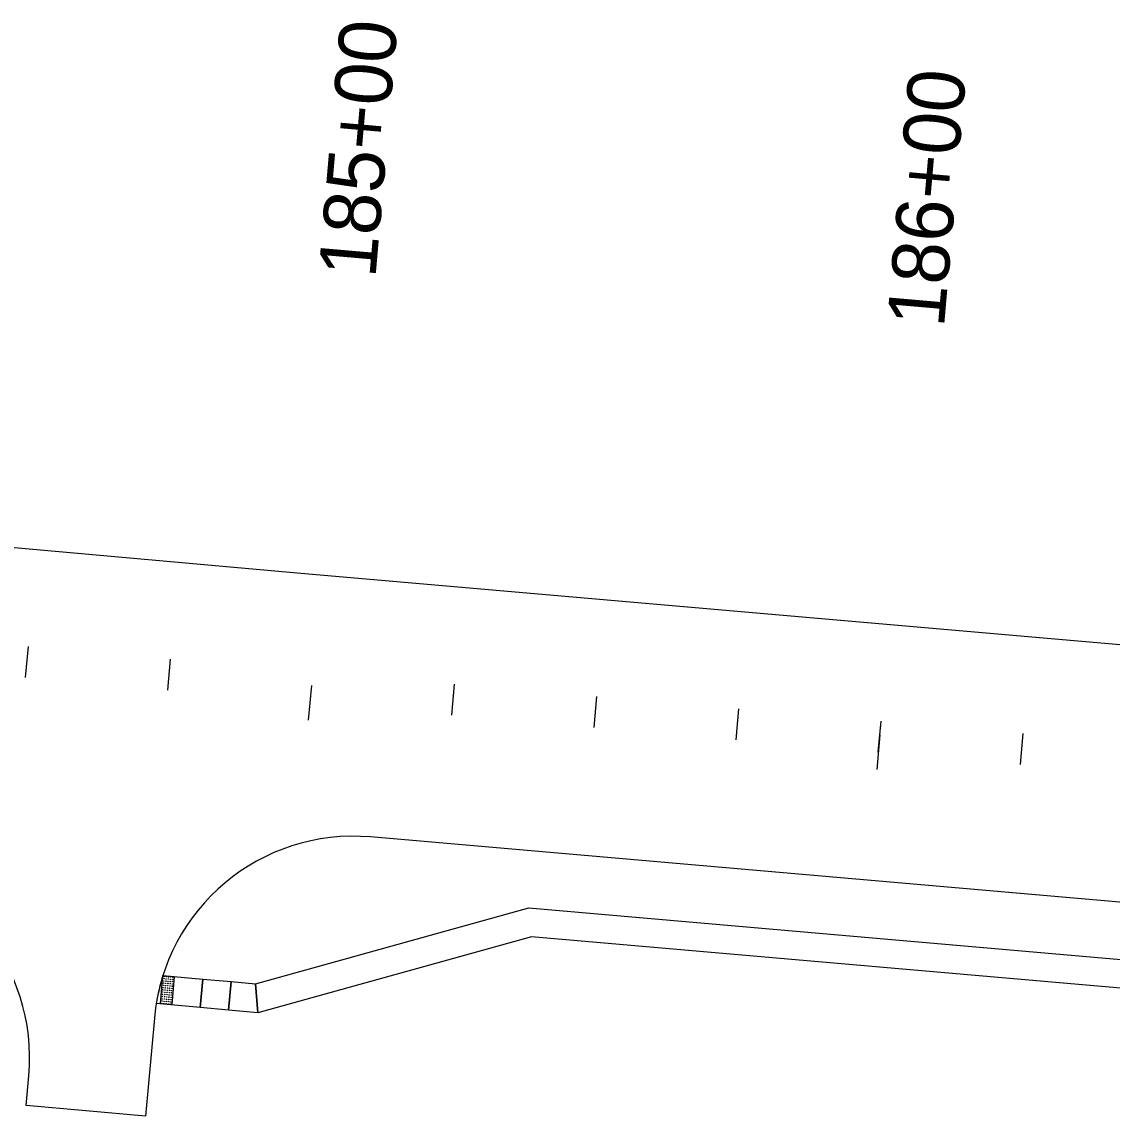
# Model space of a CAD drawing. Extents: x 20499216 to 20505321, y 7953487 to 7960535.
# Drawn here: x 20502156.3 to 20502347.4, y 7953782.6 to 7953974.4 of the extents above; entities that cross this region are included whole.
import ezdxf

# ---------------------------------------------------------------- set-up
doc = ezdxf.new("R2010")
doc.units = 0
for name, color, linetype in [('Drainage', 7, 'Continuous'), ('EXT_CU', 7, 'Continuous'), ('EXT_RR', 7, 'Continuous'), ('NamedBoundary', 7, 'Continuous'), ('Roadways', 7, 'Continuous'), ('Safety', 7, 'Continuous')]:
    doc.layers.add(name, color=color, linetype=linetype)

msp = doc.modelspace()

# ---------------------------------------------------------------- linework, layer by layer
at = {"layer": 'Drainage'}
msp.add_lwpolyline([(20502181.04, 7953807.25), (20502188.02, 7953806.62), (20502187.57, 7953801.64), (20502179.87, 7953802.33)], dxfattribs=at)
msp.add_lwpolyline([(20502197.71, 7953800.73), (20502192.55, 7953801.2), (20502193, 7953806.18), (20502197.25, 7953805.8)], close=True, dxfattribs=at)
for centre in [(20502182.5, 7953803.44), (20502182.53, 7953803.83)]:
    msp.add_circle(centre, 0.0375, dxfattribs=at)
msp.add_arc((20502214.41, 7953796.67), 35, 162.4173, 170.6968, dxfattribs=at)
at = {"layer": 'EXT_CU'}
for p, q in [((20502180.6, 7953802.27), (20502181.04, 7953807.25)), ((20502181.04, 7953807.25), (20502183.04, 7953807.07)), ((20502183.04, 7953807.07), (20502182.59, 7953802.09)), ((20502182.59, 7953802.09), (20502180.6, 7953802.27))]:
    msp.add_line(p, q, dxfattribs=at)
msp.add_lwpolyline([(20502501.09, 7953791.77), (20502245.65, 7953814.03), (20502197.71, 7953800.73), (20502197.25, 7953805.8), (20502245.18, 7953819.09), (20502501.52, 7953796.76)], close=True, dxfattribs=at)
for centre, radius in [((20502181.25, 7953807.09), 0.0375), ((20502181.25, 7953807.09), 0.0187), ((20502181.64, 7953807.05), 0.0375), ((20502181.64, 7953807.05), 0.0187), ((20502182.03, 7953807.02), 0.0375), ((20502182.03, 7953807.02), 0.0187), ((20502182.42, 7953806.98), 0.0375), ((20502182.42, 7953806.98), 0.0187), ((20502182.81, 7953806.95), 0.0375), ((20502182.81, 7953806.95), 0.0187), ((20502181.08, 7953805.14), 0.0375), ((20502181.08, 7953805.14), 0.0187), ((20502181.11, 7953805.53), 0.0375), ((20502181.11, 7953805.53), 0.0187), ((20502181.15, 7953805.92), 0.0375), ((20502181.15, 7953805.92), 0.0187), ((20502181.18, 7953806.31), 0.0375), ((20502181.18, 7953806.31), 0.0187), ((20502181.22, 7953806.7), 0.0375), ((20502181.22, 7953806.7), 0.0187), ((20502181.47, 7953805.1), 0.0375), ((20502181.47, 7953805.1), 0.0187), ((20502181.5, 7953805.49), 0.0375), ((20502181.5, 7953805.49), 0.0187), ((20502181.54, 7953805.88), 0.0375), ((20502181.54, 7953805.88), 0.0187), ((20502181.57, 7953806.27), 0.0375), ((20502181.57, 7953806.27), 0.0187), ((20502181.61, 7953806.66), 0.0375), ((20502181.61, 7953806.66), 0.0187), ((20502181.86, 7953805.07), 0.0375), ((20502181.86, 7953805.07), 0.0187), ((20502181.89, 7953805.46), 0.0375), ((20502181.89, 7953805.46), 0.0187), ((20502181.93, 7953805.85), 0.0375), ((20502181.93, 7953805.85), 0.0187), ((20502181.96, 7953806.24), 0.0375), ((20502181.96, 7953806.24), 0.0187), ((20502182, 7953806.63), 0.0375), ((20502182, 7953806.63), 0.0187), ((20502182.25, 7953805.03), 0.0375), ((20502182.25, 7953805.03), 0.0187), ((20502182.28, 7953805.42), 0.0375), ((20502182.28, 7953805.42), 0.0187), ((20502182.32, 7953805.81), 0.0375), ((20502182.32, 7953805.81), 0.0187), ((20502182.35, 7953806.2), 0.0375), ((20502182.35, 7953806.2), 0.0187), ((20502182.39, 7953806.59), 0.0375), ((20502182.39, 7953806.59), 0.0187), ((20502182.64, 7953805), 0.0375), ((20502182.64, 7953805), 0.0187), ((20502182.67, 7953805.39), 0.0375), ((20502182.67, 7953805.39), 0.0187), ((20502182.71, 7953805.78), 0.0375), ((20502182.71, 7953805.78), 0.0187), ((20502182.74, 7953806.17), 0.0375), ((20502182.74, 7953806.17), 0.0187), ((20502182.78, 7953806.56), 0.0375), ((20502182.78, 7953806.56), 0.0187), ((20502180.9, 7953803.16), 0.0375), ((20502180.9, 7953803.16), 0.0187), ((20502180.94, 7953803.58), 0.0375), ((20502180.94, 7953803.58), 0.0187), ((20502180.97, 7953803.97), 0.0375), ((20502180.97, 7953803.97), 0.0187), ((20502181.01, 7953804.36), 0.0375), ((20502181.01, 7953804.36), 0.0187), ((20502181.04, 7953804.75), 0.0375), ((20502181.04, 7953804.75), 0.0187), ((20502181.29, 7953803.13), 0.0375), ((20502181.29, 7953803.13), 0.0187), ((20502181.33, 7953803.54), 0.0375), ((20502181.33, 7953803.54), 0.0187), ((20502181.36, 7953803.93), 0.0375), ((20502181.36, 7953803.93), 0.0187), ((20502181.4, 7953804.32), 0.0375), ((20502181.4, 7953804.32), 0.0187), ((20502181.43, 7953804.71), 0.0375), ((20502181.43, 7953804.71), 0.0187), ((20502181.68, 7953803.09), 0.0375), ((20502181.68, 7953803.09), 0.0187), ((20502181.72, 7953803.51), 0.0375), ((20502181.72, 7953803.51), 0.0187), ((20502181.75, 7953803.9), 0.0375), ((20502181.75, 7953803.9), 0.0187), ((20502181.79, 7953804.29), 0.0375), ((20502181.79, 7953804.29), 0.0187), ((20502181.82, 7953804.68), 0.0375), ((20502181.82, 7953804.68), 0.0187), ((20502182.07, 7953803.06), 0.0375), ((20502182.07, 7953803.06), 0.0187), ((20502182.11, 7953803.47), 0.0375), ((20502182.11, 7953803.47), 0.0187), ((20502182.14, 7953803.86), 0.0375), ((20502182.14, 7953803.86), 0.0187), ((20502182.18, 7953804.25), 0.0375), ((20502182.18, 7953804.25), 0.0187), ((20502182.21, 7953804.64), 0.0375), ((20502182.21, 7953804.64), 0.0187), ((20502182.46, 7953803.02), 0.0375), ((20502182.46, 7953803.02), 0.0187), ((20502182.5, 7953803.44), 0.0375), ((20502182.5, 7953803.44), 0.0187), ((20502182.53, 7953803.83), 0.0375), ((20502182.53, 7953803.83), 0.0187), ((20502182.57, 7953804.22), 0.0375), ((20502182.57, 7953804.22), 0.0187), ((20502182.6, 7953804.61), 0.0375), ((20502182.6, 7953804.61), 0.0187), ((20502180.83, 7953802.38), 0.0375), ((20502180.83, 7953802.38), 0.0187), ((20502180.87, 7953802.77), 0.0375), ((20502180.87, 7953802.77), 0.0187), ((20502181.22, 7953802.35), 0.0375), ((20502181.22, 7953802.35), 0.0187), ((20502181.26, 7953802.74), 0.0375), ((20502181.26, 7953802.74), 0.0187), ((20502181.61, 7953802.31), 0.0375), ((20502181.61, 7953802.31), 0.0187), ((20502181.65, 7953802.7), 0.0375), ((20502181.65, 7953802.7), 0.0187), ((20502182, 7953802.28), 0.0375), ((20502182, 7953802.28), 0.0187), ((20502182.04, 7953802.67), 0.0375), ((20502182.04, 7953802.67), 0.0187), ((20502182.39, 7953802.24), 0.0375), ((20502182.39, 7953802.24), 0.0187), ((20502182.43, 7953802.63), 0.0375), ((20502182.43, 7953802.63), 0.0187)]:
    msp.add_circle(centre, radius, dxfattribs=at)
at = {"layer": 'EXT_RR'}
for p, q in [((20502156.99, 7953859.5), (20502157.48, 7953864.94)), ((20502181.89, 7953857.27), (20502182.38, 7953862.71)), ((20502207.06, 7953858.1), (20502206.52, 7953852.01)), ((20502231.7, 7953852.89), (20502232.17, 7953858.33)), ((20502256.6, 7953850.72), (20502257.08, 7953856.16)), ((20502281.51, 7953848.55), (20502281.98, 7953853.99)), ((20502306.68, 7953849.43), (20502306.15, 7953843.34)), ((20502331.32, 7953844.22), (20502331.79, 7953849.66))]:
    msp.add_line(p, q, dxfattribs=at)
at = {"layer": 'NamedBoundary'}
for points in [[(20501787.19, 7953915.21), (20502204.56, 7953877.83), (20502491.63, 7953852.83)], [(20502509.09, 7953806.13), (20502508.81, 7953806.16), (20502217.45, 7953831.54)], [(20502179.55, 7953799.79), (20502178.01, 7953782.62), (20502157.09, 7953784.49), (20502157.56, 7953789.67)]]:
    msp.add_lwpolyline(points, dxfattribs=at)
for centre, start, end in [((20502214.41, 7953796.67), 85.0209, 174.8834), ((20502122.7, 7953792.8), 354.8834, 84.8834)]:
    msp.add_arc(centre, 35, start, end, dxfattribs=at)
at = {"layer": 'Roadways'}
msp.add_lwpolyline([(20502187.57, 7953801.64), (20502188.02, 7953806.62), (20502193, 7953806.18), (20502192.55, 7953801.2)], close=True, dxfattribs=at)
at = {"layer": 'Safety'}
for p, q in [((20502207.06, 7953858.1), (20502206.52, 7953852.01)), ((20502306.41, 7953846.39), (20502306.89, 7953851.82))]:
    msp.add_line(p, q, dxfattribs=at)

# ---------------------------------------------------------------- texts
at = {"layer": 'EXT_RR'}
for s, p in [('185+00', (20502218.28, 7953929.34)), ('186+00', (20502317.91, 7953920.67))]:
    msp.add_text(s, height=10.02, rotation=85.0264, dxfattribs=at).set_placement(p)
at = {"layer": 'Safety'}
msp.add_text('185+00', height=10.02, rotation=85.0264, dxfattribs=at).set_placement((20502218.28, 7953929.34))

doc.saveas('drawing.dxf')
